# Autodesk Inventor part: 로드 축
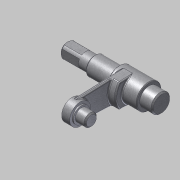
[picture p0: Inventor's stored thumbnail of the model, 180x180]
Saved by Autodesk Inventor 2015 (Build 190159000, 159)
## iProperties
Created: 2015-10
Part Number: 로드 축
Document SubType Name: Modeling
Designer: mdu
Density: 7.86 g/cm^3
Material: 강철, 연강
Mass: 151.797 g
Surface Area: 62.904 cm^2
Volume: 19.3125 cm^3
Appearance: 금속-강(스테인리스, 브러시됨)
Author: mdu
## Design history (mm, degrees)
sketch "스케치1"
  geometry: L1 (-3.325, 13.5)-(-3.325, -13.5) reference; L2 (48.675, -15.7)-(48.675, 15.7) reference; L3 (48.675, 0)-(-26.325, 0); L4 (39.675, -18.06)-(39.675, 18.06) reference; L5 (15.675, 18.855)-(15.675, -18.855) reference; L6 (6.675, 15.7)-(6.675, -15.7) reference; L7 (3.675, -10)-(3.675, 10) reference; L8 (49.675, 7.5)-(39.675, 7.5); L9 (39.675, 7.5)-(39.675, 10); L10 (39.675, 10)-(15.675, 10); L11 (15.675, 10)-(15.675, 7.5); L12 (15.675, 7.5)-(-4.325, 7.5); L13 (-4.325, 7.5)-(-4.325, 6); L14 (-4.325, 6)-(-26.325, 6); L15 (-26.325, 6)-(-26.325, 0); L16 (48.675, 0)-(49.675, 0); L17 (49.675, 0)-(49.675, 7.5); 1 further point
  constraints: 22 end point, 7 perpendicular, 4 point on line, 2 parallel, 1 collinear, 1 midpoint
  dimensions: "d0" = 15 diameter of L8 L3; "d1" = 20 diameter of L10 L3; "d2" = 12 diameter of L14 L3; "d3" = 20 distance of L11.end L12.end; "d4" = 1 distance between parallel lines of L17 L2; "d5" = 75 distance of L3.start L3.end
revolve "회전1" sketch "스케치1" stored, may be unused: angle "d6" = 90 deg
chamfer "모따기1" distance "d7" = 1; stored, may be unused: second distance "d8" = 2, angle "d9" = 45 deg
node "작업 평면1"
sketch "스케치2"
  geometry: 1 further point
sketch "스케치3"
  geometry: L1 (9.993, -0.375)-(8.494, -40.319); L2 (-8.494, -40.319)-(-9.993, -0.375); C1 r 10 at (0, 0) reference; A1 r 8.5 centre (0, -40) between (8.494, -40.319) and (-8.494, -40.319); A2 r 10 centre (0, 0) between (-9.993, -0.375) and (9.993, -0.375) reference; 1 further point
  constraints: 4 end point, 4 point on circle, 4 tangent, 1 centre point, 1 vertical alignment
  dimensions: "d12" = 17 diameter of A1; "d22" = 40 distance of A1.centre A2.centre
  node "투영된 루프1"
extrude "돌출1" join sketch "스케치3" distance "d13" = 6.5; taper "d14" = 0 deg
node "작업 평면3"
  node "작업 평면2"
extrude "돌출2" join sketch "스케치3" stored distance "d17" = 6; taper "d18" = 0 deg
sketch "스케치7"
  geometry: L1 (-9.993, -0.375)-(-8.494, -40.319) reference; L2 (8.494, -40.319)-(9.993, -0.375) reference; A1 r 10 centre (0, 0) between (-9.993, -0.375) and (9.993, -0.375) reference; A2 r 15 centre (0, 0) between (-9.574, -11.547) and (9.574, -11.547); 1 further point
  constraints: 2 point on circle, 2 point on line, 1 centre point, 1 coincident
  dimensions: "d32" = 30 diameter of A2
extrude "돌출6" join sketch "스케치7" distance "d33" = 6; taper "d34" = 0 deg
sketch "스케치5"
  geometry: C1 r 5 at (0, 0) reference; C2 r 6.5 at (0, 0); 1 further point
  constraints: 1 centre point, 1 coincident
  dimensions: "d23" = 13 diameter of C2
  node "참조8"
extrude "돌출4" join sketch "스케치5" distance "d24" = 9; taper "d25" = 0 deg
extrude "돌출5" join sketch "스케치5" distance "d26" = 1; taper "d27" = 0 deg
fillet "모깎기1" dims "d28" = 1
chamfer "모따기2" distance "d29" = 1; stored, may be unused: second distance "d30" = 2, angle "d31" = 45 deg
chamfer "모따기3" distance "d35" = 0.5; stored, may be unused: second distance "d36" = 2, angle "d37" = 45 deg
sketch "스케치8"
  geometry: L1 (-3.25, 5.044)-(3.25, 5.044); L2 (5.044, 3.25)-(5.044, -3.25); L3 (3.25, -5.044)-(-3.25, -5.044); L4 (-5.044, -3.25)-(-5.044, 3.25); 2 further points
  constraints: 8 end point, 6 perpendicular, 1 horizontal, 9 other
  dimensions: "d38" = 6.5 distance of L3.start L3.end
extrude "돌출7" cut sketch "스케치8" distance "d39" = 15; taper "d40" = 0 deg
node "솔리드1"
node "참조1"
node "참조2"
node "참조3"
node "참조4"
node "참조5"
node "참조6"
other parameters: "d10" = -8.5, "d15" = -1, "d16" = -3
